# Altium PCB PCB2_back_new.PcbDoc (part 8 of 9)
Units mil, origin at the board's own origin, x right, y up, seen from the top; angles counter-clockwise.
Board outline 6299 x 3937 mil, 4 copper layers (TopLayer, GROUND, VCC, BottomLayer); 253 components, 421 nets, 2085 pads, 712 vias.
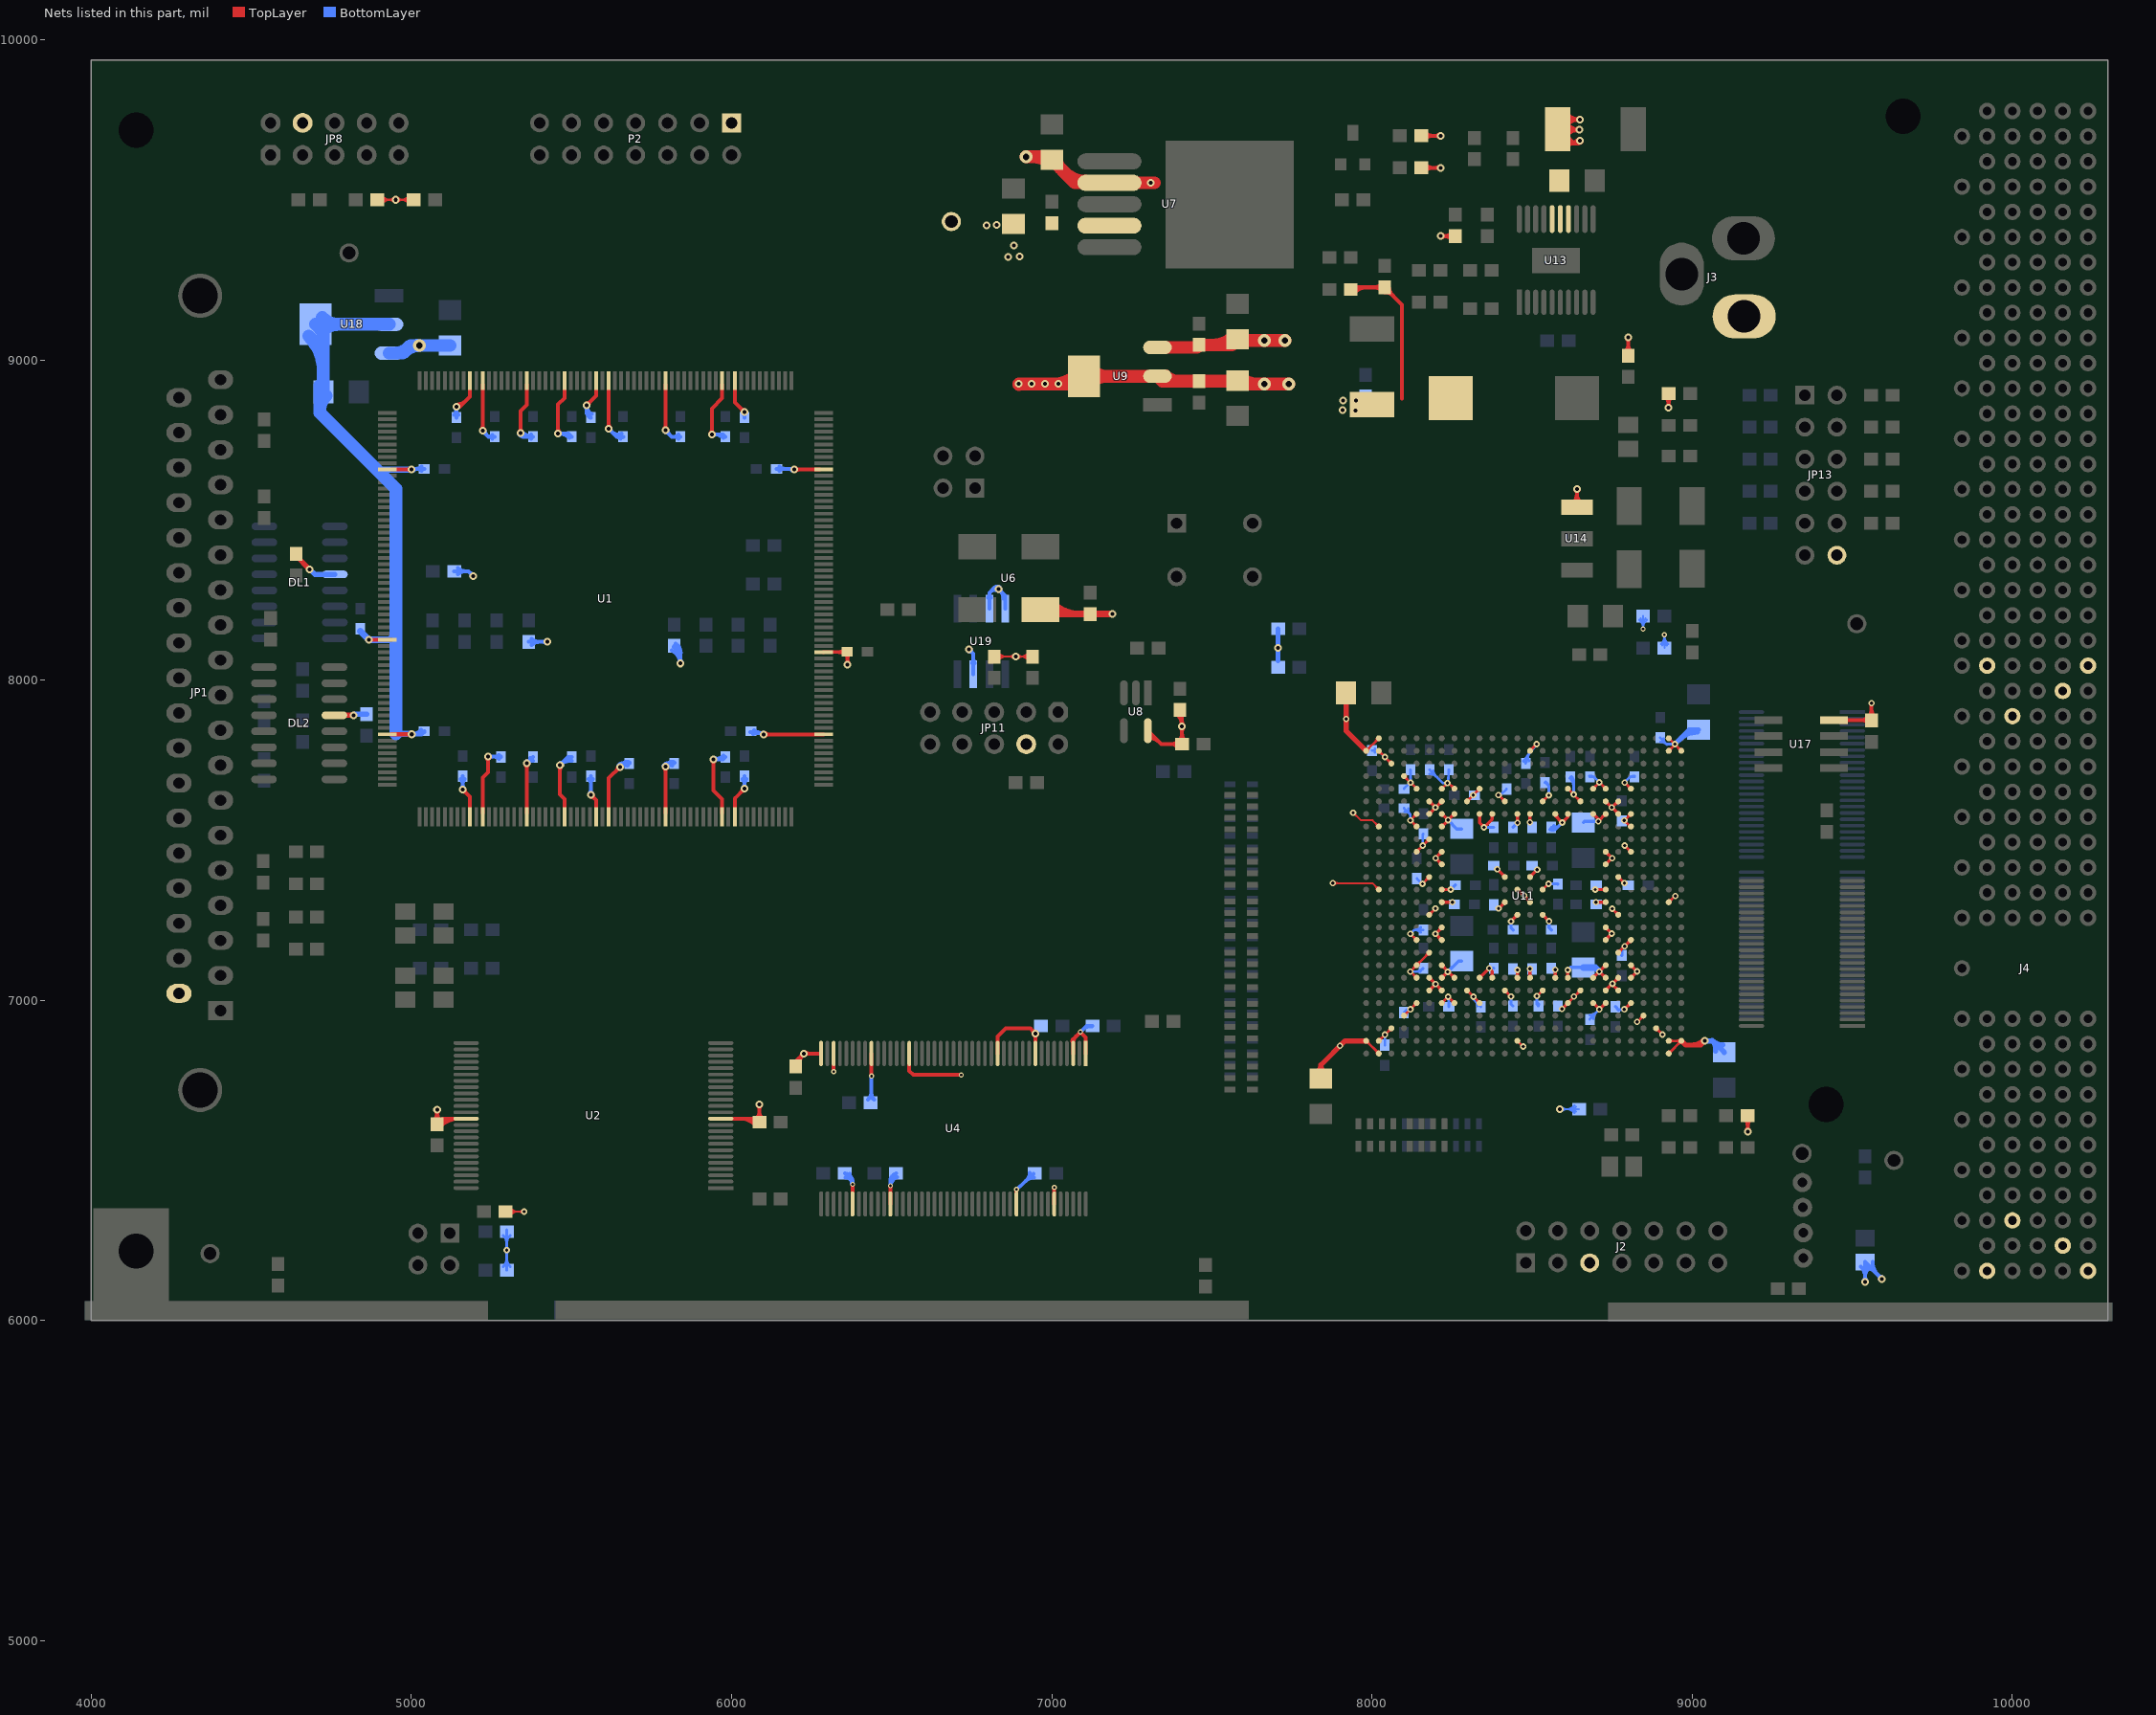
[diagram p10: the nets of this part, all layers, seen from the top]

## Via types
v1: diameter 16, hole 8, TopLayer to BottomLayer, 311 vias
v2: diameter 20, hole 10, TopLayer to BottomLayer, 202 vias
v3: diameter 24, hole 12, TopLayer to BottomLayer, 179 vias
v4: diameter 40, hole 20, TopLayer to BottomLayer, 12 vias
v5: diameter 30, hole 15, TopLayer to BottomLayer, 8 vias

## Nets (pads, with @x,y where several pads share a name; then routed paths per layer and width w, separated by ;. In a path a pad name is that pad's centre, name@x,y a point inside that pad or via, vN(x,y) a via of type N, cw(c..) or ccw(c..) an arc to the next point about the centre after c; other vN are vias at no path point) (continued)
V1.4: C23.1 C92.2 C104.1 C105.2 C106.1 C107.1 C111.1 C112.2 C113.1 C114.1 C115.1 C121.1 C122.1 C123.1 C124.1 C125.1 C126.1 C129.1 C130.2 C131.1 C135.1 C136.1 C137.1 C138.1 L1.2 R38.2 R41.2 U11.AA6 U11.AA7 U11.AA20 U11.AA21 U11.F6 U11.F7 U11.F20 U11.F21 U11.G6 U11.G7 U11.G8 U11.G10 U11.G11 U11.G13 U11.G14 U11.G16 U11.G17 U11.G19 U11.G20 U11.G21 U11.H7 U11.H20 U11.K7 U11.K20 U11.L7 U11.L20 U11.M12 U11.M14 U11.N7 U11.N13 U11.N15 U11.N20 U11.P7 U11.P12 U11.P14 U11.P20 U11.R13 U11.R15 U11.T7 U11.T20 U11.U7 U11.U20 U11.W20 U11.Y6 U11.Y7 U11.Y8 U11.Y10 U11.Y11 U11.Y13 U11.Y14 U11.Y16 U11.Y17 U11.Y19 U11.Y20 U11.Y21 | length 3757.4
  TopLayer w8: v2@8473,7327 v2@8474,7326 ; U11.P12@8532.93,7345.81 v2(8551.12,7364)
  TopLayer w10: U11.F21@8178.6,7030.85 v2(8198.23,7050.48) ; U11.F21@8178.6,7035.1 ccw(c8178.6,7045.37) 8185.86,7038.11 ccw(c8193.11,7030.85) U11.F21@8182.85,7030.85 ; U11.G21@8178.6,7065.97 cw(c8178.6,7055.7) 8185.86,7062.96 cw(c8193.11,7070.22) U11.G21@8182.85,7070.22 ; U11.G21@8178.6,7070.22 U11.F20@8217.97,7030.85 ; U11.Y21@8178.6,7582.03 v2@8198.39,7601.83 ; U11.Y21@8178.6,7586.28 ccw(c8178.6,7596.55) 8185.86,7589.29 ccw(c8193.11,7582.03) U11.Y21@8182.85,7582.03 ; U11.AA21@8178.6,7617.15 cw(c8178.6,7606.89) 8185.86,7614.14 cw(c8193.11,7621.4) U11.AA21@8182.85,7621.4 ; U11.AA21@8178.6,7621.4 v2(8198.17,7601.83) v2@8198.39,7601.83 ; 8209.74,7195.99 ccw(c8217.97,7204.21) U11.K20@8217.97,7192.58 ; 8211.11,7194.62 cw(c8204.82,7188.33) U11.K20@8213.72,7188.33 ; U11.F20@8213.72,7030.85 ccw(c8203.45,7030.85) 8210.71,7038.11 ccw(c8217.97,7045.37) U11.F20@8217.97,7035.1 ; U11.L20@8213.72,7227.7 cw(c8203.45,7227.7) 8210.71,7220.44 cw(c8217.97,7213.18) U11.L20@8217.97,7223.45 ; U11.T20@8213.72,7424.55 ccw(c8203.45,7424.55) 8210.71,7431.81 ccw(c8217.97,7439.07) U11.T20@8217.97,7428.8 ; U11.U20@8213.72,7463.92 cw(c8203.45,7463.92) 8210.71,7456.66 cw(c8217.97,7449.4) U11.U20@8217.97,7459.67 ; U11.AA20@8213.72,7621.4 cw(c8203.45,7621.4) 8210.71,7614.14 cw(c8217.97,7606.89) U11.AA20@8217.97,7617.15 ; U11.G20@8217.97,7070.22 v2(8236.57,7088.82) ; U11.G20@8217.97,7074.47 ccw(c8217.97,7084.74) 8225.23,7077.48 ccw(c8232.49,7070.22) U11.G20@8222.22,7070.22 ; U11.H20@8217.97,7105.34 cw(c8217.97,7095.07) 8225.23,7102.33 cw(c8232.49,7109.59) U11.H20@8222.22,7109.59 ; U11.H20@8217.97,7109.59 U11.G19@8257.34,7070.22 ; U11.K20@8217.97,7188.33 8217.4,7188.33 v2(8198,7207.73) U11.L20@8217.97,7227.7 ; U11.N20@8217.97,7306.44 v2(8250.57,7306.44) ; U11.P20@8217.97,7345.81 v2(8245.81,7345.81) ; U11.T20@8217.97,7424.55 v2(8199,7443.52) 8199,7444.95 U11.U20@8217.97,7463.92 ; U11.W20@8217.97,7542.66 8237.65,7562.35 v2@8238.12,7562.81 ; U11.W20@8217.97,7546.91 ccw(c8217.97,7557.18) 8225.23,7549.92 ccw(c8232.49,7542.66) U11.W20@8222.22,7542.66 ; U11.Y20@8217.97,7577.78 cw(c8217.97,7567.52) 8225.23,7574.77 cw(c8232.49,7582.03) U11.Y20@8222.22,7582.03 ; U11.Y20@8217.97,7582.03 v2(8237.19,7562.81) v2@8238.12,7562.81 ; U11.AA20@8217.97,7621.4 v2@8198.39,7601.83 ; U11.N20@8220.97,7303.43 cw(c8228.23,7296.18) 8228.23,7306.44 cw(c8228.23,7316.71) U11.N20@8220.97,7309.45 ; U11.P20@8220.97,7342.8 cw(c8228.23,7335.55) 8228.23,7345.81 cw(c8228.23,7356.08) U11.P20@8220.97,7348.82 ; U11.G19@8253.09,7070.22 ccw(c8242.82,7070.22) 8250.08,7077.48 ccw(c8257.34,7084.74) U11.G19@8257.34,7074.47 ; U11.Y19@8253.09,7582.03 cw(c8242.82,7582.03) 8250.08,7574.77 cw(c8257.34,7567.52) U11.Y19@8257.34,7577.78 ; U11.Y19@8257.34,7582.03 v2@8238.12,7562.81 ; U11.Y17@8333.07,7579.03 cw(c8325.81,7571.77) 8336.08,7571.77 cw(c8346.34,7571.77) U11.Y17@8339.08,7579.03 ; U11.G17@8336.08,7070.22 v2(8365.86,7100) 8375.45,7090.41 U11.G16@8375.45,7070.22 ; U11.G17@8336.08,7074.47 ccw(c8336.08,7084.74) 8343.34,7077.48 ccw(c8350.6,7070.22) U11.G17@8340.33,7070.22 ; U11.Y17@8336.08,7582.03 8336.08,7553.92 v2(8350,7540) 8375.45,7565.45 U11.Y16@8375.45,7582.03 ; U11.G16@8372.44,7073.23 ccw(c8365.18,7080.49) 8375.45,7080.49 ccw(c8385.71,7080.49) U11.G16@8378.46,7073.23 ; U11.Y16@8372.44,7579.03 cw(c8365.18,7571.77) 8375.45,7571.77 cw(c8385.71,7571.77) U11.Y16@8378.46,7579.03 ; v2(8391,7409) U11.R15@8414.82,7385.18 ; v2(8395.38,7287) U11.N15@8414.82,7306.44 ; U11.N15@8410.57,7306.44 cw(c8400.3,7306.44) 8407.56,7299.18 cw(c8414.82,7291.92) U11.N15@8414.82,7302.19 ; U11.R15@8410.57,7385.18 ccw(c8400.3,7385.18) 8407.56,7392.44 ccw(c8414.82,7399.7) U11.R15@8414.82,7389.43 ; v2(8434,7246.88) U11.M14@8454.19,7267.07 ; U11.M14@8449.94,7267.07 cw(c8439.67,7267.07) 8446.93,7259.81 cw(c8454.19,7252.55) U11.M14@8454.19,7262.82 ; U11.Y14@8451.18,7579.03 cw(c8443.92,7571.77) 8454.19,7571.77 cw(c8464.45,7571.77) U11.Y14@8457.2,7579.03 ; v2(8454,7095) 8454.19,7094.81 U11.G14@8454.19,7070.22 ; U11.P14@8454.19,7341.56 cw(c8454.19,7331.29) 8461.45,7338.55 cw(c8468.71,7345.81) U11.P14@8458.44,7345.81 ; U11.P14@8454.19,7345.81 8473,7327 v2(8475,7327) 8493.56,7308.44 U11.N13@8493.56,7306.44 ; v2(8454.19,7554.19) U11.Y14@8454.19,7582.03 ; U11.G13@8490.55,7073.23 ccw(c8483.29,7080.49) 8493.56,7080.49 ccw(c8503.82,7080.49) U11.G13@8496.57,7073.23 ; U11.Y13@8490.55,7579.03 cw(c8483.29,7571.77) 8493.56,7571.77 cw(c8503.82,7571.77) U11.Y13@8496.57,7579.03 ; U11.G13@8493.56,7070.22 v2(8493.56,7098.56) ; U11.R13@8493.56,7385.18 v2(8516,7407.62) ; U11.R13@8493.56,7389.43 ccw(c8493.56,7399.7) 8500.82,7392.44 ccw(c8508.08,7385.18) U11.R13@8497.81,7385.18 ; v2(8493.56,7555.56) U11.Y13@8493.56,7582.03 ; U11.M12@8532.93,7262.82 cw(c8532.93,7252.55) 8540.19,7259.81 cw(c8547.45,7267.07) U11.M12@8537.18,7267.07 ; U11.M12@8532.93,7267.07 v2(8553,7247) ; U11.G11@8569.29,7073.23 ccw(c8562.03,7080.49) 8572.3,7080.49 ccw(c8582.56,7080.49) U11.G11@8575.31,7073.23 ; U11.G11@8572.3,7070.22 v2(8572.3,7095.7) ; U11.Y11@8572.3,7582.03 8572.3,7576.7 v2(8594,7555) 8611.67,7572.67 ; U11.Y11@8576.55,7582.03 ccw(c8599.69,7582.03) 8583.33,7565.67 ; U11.Y10@8608.87,7578.83 cw(c8603.49,7572.67) 8611.67,7572.67 ; U11.G10@8611.67,7070.22 v2(8611.67,7094.67) ; U11.Y10@8611.67,7582.03 8611.67,7572.67 ; U11.Y10@8614.47,7578.83 ccw(c8619.85,7572.67) 8611.67,7572.67 ; U11.G8@8690.41,7070.22 8690.41,7070.41 8729.59,7109.59 U11.H7@8729.78,7109.59 ; U11.G8@8690.41,7074.47 ccw(c8690.41,7084.28) 8697.35,7077.35 ; U11.Y8@8690.41,7577.78 cw(c8690.41,7567.52) 8697.67,7574.77 cw(c8704.93,7582.03) U11.Y8@8694.66,7582.03 ; U11.Y8@8690.41,7582.03 8706.75,7565.69 v2(8706.75,7559) U11.Y7@8729.78,7582.03 ; U11.G8@8694.66,7070.22 cw(c8705.38,7070.22) 8697.8,7077.8 ; v2(8697.19,7345.81) U11.P7@8729.78,7345.81 ; v2(8699.56,7306.44) U11.N7@8729.78,7306.44 ; v2(8710,7090) U11.G7@8729.78,7070.22 ; 8722.2,7102.2 cw(c8729.78,7094.62) U11.H7@8729.78,7105.34 ; 8722.65,7102.65 ccw(c8715.72,7109.59) U11.H7@8725.53,7109.59 ; U11.G7@8725.53,7070.22 ccw(c8715.26,7070.22) 8722.52,7077.48 ccw(c8729.78,7084.74) U11.G7@8729.78,7074.47 ; U11.Y7@8725.53,7582.03 cw(c8715.26,7582.03) 8722.52,7574.77 cw(c8729.78,7567.52) U11.Y7@8729.78,7577.78 ; U11.N7@8726.77,7303.43 ccw(c8719.51,7296.18) 8719.51,7306.44 ccw(c8719.51,7316.71) U11.N7@8726.77,7309.45 ; U11.P7@8726.77,7342.8 ccw(c8719.51,7335.55) 8719.51,7345.81 ccw(c8719.51,7356.08) U11.P7@8726.77,7348.82 ; U11.F7@8729.78,7030.85 U11.G6@8769.15,7070.22 ; U11.F7@8729.78,7035.1 ccw(c8729.78,7045.37) 8737.04,7038.11 ccw(c8744.3,7030.85) U11.F7@8734.03,7030.85 ; U11.K7@8729.78,7188.33 8729.78,7189.26 v2(8749,7208.48) U11.L7@8729.78,7227.7 ; U11.L7@8729.78,7223.45 cw(c8729.78,7213.18) 8737.04,7220.44 cw(c8744.3,7227.7) U11.L7@8734.03,7227.7 ; U11.T7@8729.78,7424.55 8748.93,7443.7 v2(8750,7443.7) U11.U7@8729.78,7463.92 ; U11.T7@8729.78,7428.8 ccw(c8729.78,7439.07) 8737.04,7431.81 ccw(c8744.3,7424.55) U11.T7@8734.03,7424.55 ; U11.U7@8729.78,7459.67 cw(c8729.78,7449.4) 8737.04,7456.66 cw(c8744.3,7463.92) U11.U7@8734.03,7463.92 ; U11.AA7@8729.78,7617.15 cw(c8729.78,7606.89) 8737.04,7614.14 cw(c8744.3,7621.4) U11.AA7@8734.03,7621.4 ; U11.AA7@8729.78,7621.4 U11.Y6@8769.15,7582.03 ; U11.K7@8734.03,7188.33 cw(c8746.54,7188.33) 8737.69,7197.18 ; v2(8748.94,7602.24) 8768.09,7621.4 U11.AA6@8769.15,7621.4 ; v2(8750.67,7051.74) 8750.67,7049.33 U11.F6@8769.15,7030.85 U11.F6@8769.15,7032.32 ; 8760.09,7613.4 cw(c8769.15,7604.34) U11.AA6@8769.15,7617.15 ; U11.F6@8764.9,7030.85 ccw(c8754.63,7030.85) 8761.89,7038.11 ccw(c8769.15,7045.37) U11.F6@8769.15,7035.1 ; U11.G6@8764.9,7070.22 cw(c8754.63,7070.22) 8761.89,7062.96 cw(c8769.15,7055.7) U11.G6@8769.15,7065.97 ; U11.Y6@8764.9,7582.03 ccw(c8754.63,7582.03) 8761.89,7589.29 ccw(c8769.15,7596.55) U11.Y6@8769.15,7586.28
  TopLayer w12: R38.2@7933.46,9220 7940,9226.54 R41.2@8040,9226.54 8094,9172.54 8094,8879 ; R38.2@7936.62,9218.81 cw(c7955.28,9200.15) 7955.28,9226.54 ; R38.2@7945.11,9210.32 cw(c7984.25,9171.18) 7984.25,9226.54 ; R41.2@8030.32,9216.86 ccw(c8006.96,9193.5) 8006.96,9226.54 ccw(c8006.96,9259.57) R41.2@8030.32,9236.21 ; R41.2@8040,9210.88 cw(c8040,9173.09) 8066.72,9199.81 ; R41.2@8053.68,9224.57 ccw(c8081.97,9224.57) 8061.97,9204.57
  BottomLayer w10: v2(8236.57,7088.82) 8270.31,7122.57 C104.1@8280,7122.57 ; v2(8237.19,7562.81) 8264.88,7535.12 C106.1@8280,7535.12 ; v2(8245.81,7345.81) C107.1@8260,7360 ; v2(8350,7540) C115.1@8380,7540 ; v2(8365.86,7100) C111.1@8380,7100 ; v2(8434,7246.88) 8434,7226.99 C112.2@8440.99,7220 ; C126.1@8440,7540 v2(8454.19,7554.19) ; v2(8551.12,7364) 8578.99,7364 C130.2@8580,7362.99 ; v2(8553,7247) 8553,7227 C123.1@8560,7220 ; C131.1@8555.01,7533.83 ccw(c8563.51,7548.59) 8575.55,7536.55 ; C131.1@8560,7540 8579,7540 ; C131.1@8568.24,7534.34 cw(c8579,7526.95) 8579,7540 ; C131.1@8568.24,7545.66 ccw(c8579,7553.05) 8579,7540 ; v2(8594,7555) 8579,7540 ; v2(8611.67,7094.67) 8619.57,7102.57 C135.1@8660,7102.57 ; C138.1@8660,7555.12 8663.88,7559 v2(8706.75,7559)
  BottomLayer w12: v3(7949,8842) 7980,8873 C92.2@7980,8886.54 ; v3@7949,8848 ccw(c7949,8862.49) 7959.24,8852.24 ccw(c7969.49,8842) v3@7955,8842 ; v3@7954.78,8847.78 ccw(c7925.65,8876.92) C92.2@7966.45,8882.66 ; 7971.8,8864.8 ccw(c7955.48,8881.11) C92.2@7978.33,8884.33
  BottomLayer w20: C135.1@8660,7102.57 8697.43,7102.57 v2(8710,7090)
  other v3: 7908,8843 7909,8873 7950,8873
V1.5: C13.1 C17.2 C49.1 C51.1 C52.1 C53.1 C54.1 C58.1 C60.1 C61.1 C63.1 C64.1 C67.1 C69.1 FB6.1 FB7.1 U1.72 U1.81 U1.90 U1.97 U1.103 U1.110 U1.191 U1.198 U1.204 U1.211 U1.220 U1.229 U9.2 | length 5264.2
  TopLayer w8: 5220,8857 5222.14,8859.14 ; U1.97@5478.05,8922.31 U1.97@5480,8920.35
  TopLayer w12: v3@5217.9,8783.1 ccw(c5207.66,8793.34) 5222.14,8793.34 ccw(c5236.63,8793.34) v3@5226.38,8783.1 ; U1.191@5222.14,7585.69 5222.14,7695.14 5239,7712 v3(5239,7761) ; v3(5222.14,8778.86) U1.110@5222.14,8922.31 ; v3@5234.76,7756.76 cw(c5224.51,7746.51) 5239,7746.51 cw(c5253.49,7746.51) v3@5243.24,7756.76 ; v3@5336.76,8775.24 ccw(c5326.51,8785.49) 5341,8785.49 ccw(c5355.49,8785.49) v3@5345.24,8775.24 ; v3(5341,8771) 5341,8840.13 5359.94,8859.06 U1.103@5359.94,8922.31 ; v3@5355.69,7735.69 cw(c5345.45,7725.45) 5359.94,7725.45 cw(c5374.42,7725.45) v3@5364.18,7735.69 ; U1.198@5359.94,7585.69 v3(5359.94,7739.94) ; v3@5453.76,8774.24 ccw(c5443.51,8784.49) 5458,8784.49 ccw(c5472.49,8784.49) v3@5462.24,8774.24 ; v3(5458,8770) 5458,8861 5478.05,8881.05 U1.97@5478.05,8922.31 ; v3@5459.76,7730.76 cw(c5449.51,7720.51) 5464,7720.51 cw(c5478.49,7720.51) v3@5468.24,7730.76 ; v3(5464,7735) 5464,7643 5478.05,7628.95 U1.204@5478.05,7585.69 ; v3@5611.6,8789.4 ccw(c5601.36,8799.64) 5615.84,8799.64 ccw(c5630.33,8799.64) v3@5620.09,8789.4 ; U1.211@5615.84,7585.69 5615.84,7693.84 v3(5651,7729) ; v3(5615.84,8785.16) U1.90@5615.84,8922.31 ; v3@5645,7729 cw(c5630.51,7729) 5640.76,7718.76 cw(c5651,7708.51) v3@5651,7723 ; v3@5788.77,7725.77 cw(c5778.52,7715.52) 5793.01,7715.52 cw(c5807.49,7715.52) v3@5797.25,7725.77 ; v3@5788.77,8784.23 ccw(c5778.52,8794.48) 5793.01,8794.48 ccw(c5807.49,8794.48) v3@5797.25,8784.23 ; U1.220@5793.01,7585.69 v3(5793.01,7730.01) ; v3(5793.01,8779.99) U1.81@5793.01,8922.31 ; v3@5933.76,8771.24 ccw(c5923.51,8781.49) 5938,8781.49 ccw(c5952.49,8781.49) v3@5942.24,8771.24 ; v3(5938,8767) 5938,8848 5970.17,8880.17 U1.72@5970.17,8922.31 ; v3@5938.76,7748.76 cw(c5928.51,7738.51) 5943,7738.51 cw(c5957.49,7738.51) v3@5947.24,7748.76 ; v3(5943,7753) 5943,7655 5970.17,7627.83 U1.229@5970.17,7585.69
  TopLayer w40: v3@6897,8923 v3(6897,8925) U9.2@7095,8925 ; 7005.85,8925 ccw(c7005.85,9028.15) U9.2@7078.79,8955.21 ; 7049.3,8925 cw(c7049.3,8883.3) U9.2@7078.79,8912.79 ; U9.2@7100,8949 U9.2@7330,8949 7345.54,8933.46 7578.35,8933.46 7586.81,8925 v4(7740,8925) ; U9.2@7121.21,8927.79 cw(c7172.43,8876.57) 7172.43,8949 cw(c7172.43,9021.43) U9.2@7121.21,8970.21 ; U9.2@7354.71,8949.71 ccw(c7393.92,8988.92) 7393.92,8933.46 ; 7544.32,8933.46 ccw(c7544.32,8966.86) C13.1@7567.93,8943.25 ; C13.1@7592.07,8943.25 ccw(c7636.12,8987.3) 7636.12,8925
  BottomLayer w12: v3@5222.14,8772.86 cw(c5222.14,8758.37) 5232.38,8768.62 cw(c5242.63,8778.86) v3@5228.14,8778.86 ; v3(5222.14,8778.86) 5241,8760 ; v3(5239,7761) 5279,7761 C49.1@5280,7760 ; v3@5243.24,7756.76 cw(c5253.49,7746.51) 5253.49,7761 cw(c5253.49,7775.49) v3@5243.24,7765.24 ; C51.1@5253.04,8754.3 ccw(c5241,8744.45) 5241,8760 ; C51.1@5253.04,8765.7 cw(c5241,8775.55) 5241,8760 ; 5255.86,7761 cw(c5255.86,7735.86) C49.1@5273.64,7753.64 ; C51.1@5260,8760 5241,8760 ; 5260.69,7761 ccw(c5260.69,7779.31) C49.1@5273.64,7766.36 ; v3@5336.6,8766.92 ccw(c5352.47,8781.66) 5352.47,8760 ; v3@5341,8765 cw(c5341,8750.51) 5351.24,8760.76 cw(c5361.49,8771) v3@5347,8771 ; v3(5341,8771) 5352,8760 C53.1@5380,8760 cw(c5380,8807.23) v3@5345.4,8775.08 ; v3(5359.94,7739.94) C52.1@5380,7760 ; v3@5359.94,7745.94 ccw(c5359.94,7760.42) 5370.18,7750.18 ccw(c5380.42,7739.94) v3@5365.94,7739.94 ; v3@5360.37,7740.37 cw(c5380,7720.74) C52.1@5380,7748.5 ; FB6.1@5366,8119.54 v3(5424.54,8119.54) ; C52.1@5366.4,7746.4 ccw(c5355.31,7757.5) C52.1@5371,7757.5 ; C53.1@5373.64,8753.64 ccw(c5358.27,8738.27) 5358.27,8760 ccw(c5358.27,8781.73) C53.1@5373.64,8766.36 ; FB6.1@5375.68,8109.86 cw(c5399.04,8086.5) 5399.04,8119.54 cw(c5399.04,8152.57) FB6.1@5375.68,8129.21 ; v3@5420.29,8115.29 ccw(c5410.05,8105.05) 5410.05,8119.54 ccw(c5410.05,8134.02) v3@5420.29,8123.78 ; v3(5458,8770) 5490,8770 C58.1@5500,8760 ; v3@5460.17,8770 cw(c5460.17,8722.67) C58.1@5493.64,8756.14 ; v3@5461.59,7732.59 cw(c5500,7694.18) C54.1@5500,7748.5 ; v3@5462.24,8765.76 cw(c5472.49,8755.51) 5472.49,8770 cw(c5472.49,8784.49) v3@5462.24,8774.24 ; v3(5464,7735) 5489,7760 C54.1@5500,7760 ; v3@5464,7741 ccw(c5464,7755.49) 5474.24,7745.24 ccw(c5484.49,7735) v3@5470,7735 ; 5482.08,7753.08 cw(c5500,7735.15) C54.1@5500,7760.5 ; v3@5615.84,8779.16 cw(c5615.84,8764.67) 5626.09,8774.91 cw(c5636.33,8785.16) v3@5621.84,8785.16 ; v3(5615.84,8785.16) 5641,8760 ; 5626.59,8774.41 ccw(c5643.78,8791.6) C61.1@5655.62,8770.36 ; 5637.83,8763.17 ccw(c5651.82,8777.17) C61.1@5661.46,8759.88 ; v3@5645.76,7731.93 cw(c5659.53,7724.23) 5659.53,7740 ; v3(5651,7729) 5662,7740 ; v3@5651,7735 ccw(c5651,7749.49) 5661.24,7739.24 ccw(c5671.49,7729) v3@5657,7729 ; v3@5653,7731 cw(c5664.86,7719.14) C60.1@5674.71,7732.72 ; C61.1@5653.04,8754.3 ccw(c5641,8744.45) 5641,8760 ; C61.1@5653.04,8765.7 cw(c5641,8775.55) 5641,8760 ; v3@5655.56,7733.56 cw(c5674.13,7714.99) C60.1@5680.76,7740.4 ; v3@5656.24,7726.07 cw(c5680,7712.77) C60.1@5680,7740 5662,7740 ; C61.1@5660,8760 5641,8760 ; 5662.94,7740.94 cw(c5673.22,7730.66) C60.1@5681.76,7742.43 ; C60.1@5672.8,7734.6 ccw(c5662,7726.5) 5662,7740 ; C60.1@5672.8,7745.4 cw(c5662,7753.5) 5662,7740 ; v3@5787.75,7732.89 cw(c5799.75,7726.32) 5799.75,7740 ; v3(5793.01,7730.01) 5803,7740 ; v3@5793.01,8773.99 cw(c5793.01,8759.51) 5803.25,8769.75 cw(c5813.49,8779.99) v3@5799.01,8779.99 ; v3(5793.01,8779.99) 5813,8760 C64.1@5840,8760 ; v3@5793.11,7736.01 ccw(c5793.36,7749.64) 5803,7740 ; v3@5794.5,7731.5 cw(c5805.29,7720.71) C63.1@5814.54,7732.84 ; v3@5797.47,7734.47 cw(c5814.11,7717.83) C63.1@5820.86,7740.37 ; v3@5798.27,7727.13 cw(c5820,7715.23) C63.1@5820,7740 5803,7740 ; v3@5799.01,7730.11 cw(c5812.64,7730.36) 5803,7740 ; 5804.2,7741.2 cw(c5813.69,7731.72) C63.1@5821.82,7742.39 ; C63.1@5812.56,7734.94 ccw(c5803,7728.45) 5803,7740 ; C63.1@5812.56,7745.06 cw(c5803,7751.55) 5803,7740 ; FB7.1@5813.54,8092.5 cw(c5789.89,8048.33) v3@5840,8048.33 ; FB7.1@5819.2,8103.08 cw(c5800.62,8068.36) 5840,8068.36 ; FB7.1@5820,8106.54 5840,8086.54 v3(5840,8052) ; FB7.1@5822.64,8091.14 cw(c5826.57,8071.14) 5840.98,8085.55 cw(c5858.66,8103.23) FB7.1@5833.68,8104.09 ; FB7.1@5824.87,8113.66 cw(c5811.34,8088.4) 5840,8088.4 ; C64.1@5833.64,8753.64 ccw(c5818.27,8738.27) 5818.27,8760 ccw(c5818.27,8781.73) C64.1@5833.64,8766.36 ; v3@5835.76,8056.24 ccw(c5825.51,8066.49) 5840,8066.49 ccw(c5854.49,8066.49) v3@5844.24,8056.24 ; v3(5938,8767) 5973,8767 C69.1@5980,8760 ; v3@5942.24,8762.76 cw(c5952.49,8752.51) 5952.49,8767 cw(c5952.49,8781.49) v3@5942.24,8771.24 ; v3(5943,7753) 5973,7753 C67.1@5980,7760 ; v3@5947.24,7748.76 cw(c5957.49,7738.51) 5957.49,7753 cw(c5957.49,7767.49) v3@5947.24,7757.24 ; v3@5947.41,7753 ccw(c5947.41,7790.09) C67.1@5973.64,7763.86 ; v3@5947.41,8767 cw(c5947.41,8729.91) C69.1@5973.64,8756.14
  other v3: 6937,8925 6978,8925 7020,8925
  other v4: 7664,8925
V2.5: C38.1 C40.1 C45.1 C47.1 U1.130 U1.157 U1.172 U18.2 | length 2667
  TopLayer w12: v3(4866.95,8126.05) U1.157@4937.69,8126.05 ; U1.172@4937.69,7830.77 v3(5000.77,7830.77) ; U1.130@4937.69,8657.54 v3(5000.54,8657.54) ; v3@4996.3,8653.3 ccw(c4986.06,8643.06) 4986.06,8657.54 ccw(c4986.06,8672.03) v3@4996.3,8661.79 ; v3@4996.53,7826.53 ccw(c4986.29,7816.29) 4986.29,7830.77 ccw(c4986.29,7845.26) v3@4996.53,7835.01
  BottomLayer w8: C40.1@4840,8153 C40.1@4840,8160 ; v3(5000.54,8657.54) v3@5003,8660
  BottomLayer w12: v3@5003,8660 C47.1@5040,8660 ; v3@5004.79,8653.3 cw(c5020.96,8637.13) 5020.96,8660 ; v3@5005.01,7826.53 cw(c5015.26,7816.29) 5015.26,7830.77 cw(c5015.26,7845.26) v3@5005.01,7835.01 ; C45.1@5024.95,7830.77 ccw(c5024.95,7849.53) C45.1@5039.89,7838.19 ; C45.1@5030.33,7845.44 cw(c5000.77,7867.88) v3(5000.77,7830.77) 5030.77,7830.77 C45.1@5040,7840 ; C47.1@5031.14,8653.64 ccw(c5015.77,8638.27) 5015.77,8660 ccw(c5015.77,8681.73) C47.1@5031.14,8666.36
  BottomLayer w20: C40.1@4840,8153 v3(4866.95,8126.05) 4931.05,8126.05 4952,8147 ; 4901.54,8657.54 v3(5000.54,8657.54) ; 4952,7832 4999.54,7832 v3(5000.77,7830.77)
  BottomLayer w40: U18.2@4678.79,9074.79 cw(c4567.5,8963.5) 4724.88,8963.5 ; 4713.46,8840.75 cw(c4780.2,8840.75) C38.1@4733.01,8887.93 ; C38.1@4713.46,8920 4713.46,8835.54 4952,8597 4952,7832 ; U18.2@4721.21,9089.79 cw(c4772.43,9038.57) 4772.43,9111 cw(c4772.43,9183.43) U18.2@4721.21,9132.21 ; C38.1@4724.88,8900 4724.88,9086.12 U18.2@4700,9111 U18.2@4930,9111
V3.3: C1.1 C2.1 C5.2 C7.1 C8.2 C10.1 C12.1 C15.2 C16.2 C19.2 C20.1 C21.1 C37.2 C44.1 C48.1 C56.1 C57.1 C71.1 C73.1 C75.1 C77.1 C79.2 C80.2 C81.2 C82.2 C83.2 C84.2 C91.1 C93.1 C94.1 C95.1 C96.1 C97.1 C98.1 C99.1 C100.1 C101.1 C102.1 C103.1 C108.1 C109.1 C110.1 C116.1 C119.1 C120.1 C127.1 C128.1 C132.1 C133.1 C134.1 C139.1 C140.1 C141.1 C142.1 C143.1 C144.1 C145.1 C146.1 C147.1 DL1.4 DL2.13 FB4.1 J2.5 JP1.20 JP8.4 JP11.4 P2.1 pad.9 R15.2 R18.2 R19.2 R24.2 R26.2 R30.2 R56.2 R63.1 R64.1 R65.2 R76.1 R77.1 R80.2 R81.2 R82.2 U1.9 U1.22 U1.51 U1.70 U1.92 U1.112 U1.189 U1.209 U1.231 U2.12 U2.37 U4.1 U4.3 U4.9 U4.15 U4.29 U4.35 U4.41 U4.43 U4.49 U4.55 U4.75 U4.81 U6.4 U7.4 U8.5 U11.A2 U11.A25 U11.AA9 U11.AA12 U11.AA15 U11.AA18 U11.AB5 U11.AB7 U11.AB8 U11.AB10 U11.AB17 U11.AB19 U11.AB20 U11.AB22 U11.AC23 U11.AD24 U11.AE1 U11.AE2 U11.AE13 U11.AE25 U11.AE26 U11.AF2 U11.AF25 U11.B1 U11.B2 U11.B14 U11.B25 U11.B26 U11.C3 U11.C24 U11.D4 U11.D23 U11.E5 U11.E7 U11.E8 U11.E10 U11.E17 U11.E19 U11.E20 U11.E22 U11.F9 U11.F12 U11.F15 U11.F18 U11.G5 U11.G22 U11.H5 U11.H22 U11.J6 U11.J21 U11.K5 U11.K22 U11.M6 U11.M21 U11.N2 U11.P25 U11.R6 U11.R21 U11.U5 U11.U22 U11.V21 U11.W5 U11.W22 U11.W25 U11.Y5 U11.Y22 U14.1 U17.8 U19.3 U19.7 U19.8 | length 14541.5
  TopLayer w6: R19.2@5293.46,6340 v2(5352,6340) ; R19.2@5302.99,6332.44 cw(c5321.23,6314.2) 5321.23,6340 cw(c5321.23,6365.8) R19.2@5302.99,6347.56 ; R19.2@5307.23,6328.2 cw(c5335.71,6299.72) 5335.71,6340 cw(c5335.71,6380.28) R19.2@5307.23,6351.8 ; v2@5347.05,6335.05 ccw(c5335.1,6323.1) 5335.1,6340 ccw(c5335.1,6356.9) v2@5347.05,6344.95 ; R24.2@6820,8073.46 R26.2@6940,8073.46 ; R24.2@6827.56,8065.91 cw(c6845.8,8047.67) 6845.8,8073.46 cw(c6845.8,8099.26) R24.2@6827.56,8081.02 ; R24.2@6831.8,8061.67 cw(c6860.28,8033.18) 6860.28,8073.46 cw(c6860.28,8113.75) R24.2@6831.8,8085.26 ; v3@6881.64,8067.1 ccw(c6866.27,8051.74) 6866.27,8073.46 ccw(c6866.27,8095.19) v3@6881.64,8079.83 ; v3@6894.36,8067.1 cw(c6909.73,8051.74) 6909.73,8073.46 cw(c6909.73,8095.19) v3@6894.36,8079.83 ; R26.2@6928.2,8061.67 ccw(c6899.72,8033.18) 6899.72,8073.46 ccw(c6899.72,8113.75) R26.2@6928.2,8085.26 ; R26.2@6932.44,8065.91 ccw(c6914.2,8047.67) 6914.2,8073.46 ccw(c6914.2,8099.26) R26.2@6932.44,8081.02 ; v2(7877,7366) 8000.93,7366 U11.P25@8021.12,7345.81 ; v2@7881.95,7361.05 cw(c7893.9,7349.1) 7893.9,7366 cw(c7893.9,7382.9) v2@7881.95,7370.95 ; v2(7941,7586) 7965,7562 8001.78,7562 U11.W25@8021.12,7542.66 ; U11.P25@8014.87,7345.81 ccw(c7999.77,7345.81) 8010.44,7356.48 ccw(c8021.12,7367.16) U11.P25@8021.12,7352.06 ; U11.W25@8014.87,7542.66 ccw(c7999.77,7542.66) 8010.44,7553.33 ccw(c8021.12,7564.01) U11.W25@8021.12,7548.91
  TopLayer w8: R15.2@4893.46,9500 R18.2@5006.54,9500 ; R15.2@4906.52,9488.91 cw(c4933.3,9462.13) 4933.3,9500 cw(c4933.3,9537.87) R15.2@4906.52,9511.09 ; v3@4945.34,9494.34 ccw(c4931.69,9480.69) 4931.69,9500 ccw(c4931.69,9519.31) v3@4945.34,9505.66 ; v3@4956.66,9494.34 cw(c4970.31,9480.69) 4970.31,9500 cw(c4970.31,9519.31) v3@4956.66,9505.66 ; R18.2@4993.48,9488.91 ccw(c4966.7,9462.13) 4966.7,9500 ccw(c4966.7,9537.87) R18.2@4993.48,9511.09 ; U11.B26@7981.75,6868.12 cw(c7981.75,6855.44) 7990.71,6864.4 cw(c7999.68,6873.37) U11.B26@7987,6873.37 ; U11.B26@7981.75,6873.37 U11.A25@8021.12,6834 ; U11.AE26@7981.75,7778.88 U11.AF25@8021.12,7818.25 ; U11.AE26@7981.75,7784.13 ccw(c7981.75,7796.81) 7990.71,7787.85 ccw(c7999.68,7778.88) U11.AE26@7987,7778.88 ; U11.A25@8015.87,6834 ccw(c8003.19,6834) 8012.15,6842.97 ccw(c8021.12,6851.93) U11.A25@8021.12,6839.25 ; U11.AF25@8015.87,7818.25 cw(c8003.19,7818.25) 8012.15,7809.29 cw(c8021.12,7800.32) U11.AF25@8021.12,7813 ; U11.B25@8021.12,6873.37 U11.C24@8060.49,6912.74 ; U11.B25@8021.12,6878.62 ccw(c8021.12,6891.3) 8030.08,6882.34 ccw(c8039.05,6873.37) U11.B25@8026.37,6873.37 ; U11.AE25@8021.12,7773.63 cw(c8021.12,7760.95) 8030.08,7769.92 cw(c8039.05,7778.88) U11.AE25@8026.37,7778.88 ; U11.AE25@8021.12,7778.88 U11.AD24@8060.49,7739.51 ; U11.C24@8055.24,6912.74 cw(c8042.56,6912.74) 8051.52,6903.77 cw(c8060.49,6894.81) U11.C24@8060.49,6907.49 ; U11.AD24@8055.24,7739.51 ccw(c8042.56,7739.51) 8051.52,7748.48 ccw(c8060.49,7757.44) U11.AD24@8060.49,7744.76 ; U11.D23@8099.86,6952.11 8119.87,6972.13 U11.E22@8139.23,6991.48 ; U11.D23@8099.86,6957.36 ccw(c8099.86,6970.04) 8108.82,6961.08 ccw(c8117.79,6952.11) U11.D23@8105.11,6952.11 ; U11.AC23@8099.86,7694.89 cw(c8099.86,7682.21) 8108.82,7691.18 cw(c8117.79,7700.14) U11.AC23@8105.11,7700.14 ; U11.AC23@8099.86,7700.14 U11.AB22@8139.23,7660.77 ; v2(8120,7207.56) U11.K22@8139.23,7188.33 ; 8130.13,7079.51 cw(c8120.84,7070.22) U11.G22@8133.98,7070.22 ; 8130.58,7079.05 ccw(c8139.23,7087.7) U11.G22@8139.23,7075.47 ; U11.E22@8133.98,6991.48 cw(c8121.3,6991.48) 8130.26,6982.51 cw(c8139.23,6973.55) U11.E22@8139.23,6986.23 ; U11.H22@8133.98,7109.59 cw(c8121.3,7109.59) 8130.26,7100.63 cw(c8139.23,7091.66) U11.H22@8139.23,7104.34 ; U11.K22@8133.98,7188.33 ccw(c8121.3,7188.33) 8130.26,7197.3 ccw(c8139.23,7206.26) U11.K22@8139.23,7193.58 ; U11.W22@8133.98,7542.66 ccw(c8121.3,7542.66) 8130.26,7551.63 ccw(c8139.23,7560.59) U11.W22@8139.23,7547.91 ; U11.Y22@8133.98,7582.03 cw(c8121.3,7582.03) 8130.26,7573.07 cw(c8139.23,7564.1) U11.Y22@8139.23,7576.78 ; U11.G22@8139.23,7070.22 8139.23,7070.41 v2(8119.64,7090) U11.J21@8178.6,7148.96 ; U11.H22@8139.23,7114.84 ccw(c8139.23,7127.52) 8148.19,7118.56 ccw(c8157.16,7109.59) U11.H22@8144.48,7109.59 ; U11.U22@8139.23,7463.92 U11.V21@8178.6,7503.29 ; U11.U22@8139.23,7469.17 ccw(c8139.23,7481.85) 8148.19,7472.89 ccw(c8157.16,7463.92) U11.U22@8144.48,7463.92 ; U11.W22@8139.23,7542.66 v2(8120,7561.89) 8120,7562.8 U11.Y22@8139.23,7582.03 ; v2(8157.42,7364) U11.R21@8178.6,7385.18 ; U11.J21@8173.35,7148.96 cw(c8160.67,7148.96) 8169.63,7140 cw(c8178.6,7131.03) U11.J21@8178.6,7143.71 ; U11.R21@8173.35,7385.18 cw(c8160.67,7385.18) 8169.63,7376.22 cw(c8178.6,7367.25) U11.R21@8178.6,7379.93 ; U11.V21@8173.35,7503.29 cw(c8160.67,7503.29) 8169.63,7494.33 cw(c8178.6,7485.36) U11.V21@8178.6,7498.04 ; U11.M21@8178.6,7267.07 v2(8198,7286.47) ; U11.M21@8178.6,7272.32 ccw(c8178.6,7285) 8187.56,7276.04 ccw(c8196.53,7267.07) U11.M21@8183.85,7267.07 ; U11.E20@8217.97,6991.48 8237.49,7011 v2(8237.82,7011) U11.E19@8257.34,6991.48 ; U11.E20@8217.97,6996.73 ccw(c8217.97,7009.41) 8226.93,7000.45 ccw(c8235.9,6991.48) U11.E20@8223.22,6991.48 ; U11.AB20@8217.97,7660.77 v2(8235.2,7678) 8240.11,7678 U11.AB19@8257.34,7660.77 ; U11.E19@8252.09,6991.48 ccw(c8239.41,6991.48) 8248.37,7000.45 ccw(c8257.34,7009.41) U11.E19@8257.34,6996.73 ; U11.AB19@8252.09,7660.77 ccw(c8239.41,7660.77) 8248.37,7669.74 ccw(c8257.34,7678.7) U11.AB19@8257.34,7666.02 ; U11.F18@8296.71,7025.6 cw(c8296.71,7011.85) 8306.43,7021.57 ; U11.F18@8296.71,7030.85 8297.15,7030.85 v2(8317,7011) U11.E17@8336.08,6991.48 ; U11.AA18@8296.71,7621.4 U11.AB17@8336.08,7660.77 ; U11.AA18@8296.71,7626.65 ccw(c8296.71,7639.33) 8305.67,7630.37 ccw(c8314.64,7621.4) U11.AA18@8301.96,7621.4 ; U11.F18@8301.96,7030.85 ccw(c8313.57,7030.85) 8305.36,7022.64 ; U11.E17@8330.83,6991.54 ccw(c8318.15,6991.69) 8327.22,7000.55 ccw(c8336.28,7009.41) U11.E17@8336.14,6996.73 ; U11.AB17@8330.83,7660.77 cw(c8318.15,7660.77) 8327.11,7651.81 cw(c8336.08,7642.84) U11.AB17@8336.08,7655.52 ; v2(8395,7641.22) U11.AA15@8414.82,7621.4 ; U11.AA15@8409.57,7621.4 ccw(c8396.89,7621.4) 8405.85,7630.37 ccw(c8414.82,7639.33) U11.AA15@8414.82,7626.65 ; U11.F15@8414.82,7025.6 cw(c8414.82,7012.92) 8423.78,7021.88 cw(c8432.75,7030.85) U11.F15@8420.07,7030.85 ; U11.F15@8414.82,7030.85 v2(8434,7011.67) ; U11.B14@8454.19,6873.37 v2(8472,6855.56) ; U11.AE13@8493.47,7784.13 ccw(c8493.27,7796.81) 8502.38,7787.99 ccw(c8511.49,7779.17) U11.AE13@8498.81,7778.97 ; U11.AE13@8493.56,7778.88 v2(8514,7800) ; v2(8515,7012.92) U11.F12@8532.93,7030.85 ; U11.AA12@8532.93,7621.4 v2(8552,7640.47) ; U11.AA12@8532.93,7626.65 ccw(c8532.93,7639.33) 8541.89,7630.37 ccw(c8550.86,7621.4) U11.AA12@8538.18,7621.4 ; U11.E10@8611.67,6991.48 U11.F9@8651.04,7030.85 ; U11.E10@8611.67,6996.73 ccw(c8611.67,7009.41) 8620.63,7000.45 ccw(c8629.6,6991.48) U11.E10@8616.92,6991.48 ; U11.AB10@8611.67,7660.77 U11.AA9@8651.04,7621.4 ; U11.F9@8645.79,7030.85 cw(c8633.11,7030.85) 8642.07,7021.88 cw(c8651.04,7012.92) U11.F9@8651.04,7025.6 ; U11.AA9@8645.79,7621.4 ccw(c8633.11,7621.4) 8642.07,7630.37 ccw(c8651.04,7639.33) U11.AA9@8651.04,7626.65 ; U11.AB8@8690.41,7660.77 8710,7680.36 v2(8710,7680.55) U11.AB7@8729.78,7660.77 ; U11.AB8@8690.41,7666.02 ccw(c8690.41,7678.7) 8699.37,7669.74 ccw(c8708.34,7660.77) U11.AB8@8695.66,7660.77 ; U11.AB7@8724.53,7660.77 ccw(c8711.85,7660.77) 8720.81,7669.74 ccw(c8729.78,7678.7) U11.AB7@8729.78,7666.02 ; v2(8750,7286.22) U11.M6@8769.15,7267.07 ; U11.M6@8763.9,7267.07 ccw(c8751.22,7267.07) 8760.18,7276.04 ccw(c8769.15,7285) U11.M6@8769.15,7272.32 ; U11.R6@8769.15,7379.93 cw(c8769.15,7367.25) 8778.12,7376.22 cw(c8787.08,7385.18) U11.R6@8774.4,7385.18 ; U11.R6@8769.15,7385.18 v2(8788.33,7366) ; v2(8789,7483.44) U11.U5@8808.52,7463.92 ; v2(8789,7680.29) U11.AB5@8808.52,7660.77 ; 8800.73,7548.78 cw(c8794.62,7542.66) U11.W5@8803.27,7542.66 ; U11.U5@8803.27,7463.92 ccw(c8790.59,7463.92) 8799.55,7472.89 ccw(c8808.52,7481.85) U11.U5@8808.52,7469.17 ; U11.Y5@8803.27,7582.03 cw(c8790.59,7582.03) 8799.55,7573.07 cw(c8808.52,7564.1) U11.Y5@8808.52,7576.78 ; U11.AB5@8803.27,7660.77 ccw(c8790.59,7660.77) 8799.55,7669.74 ccw(c8808.52,7678.7) U11.AB5@8808.52,7666.02 ; U11.W5@8808.52,7542.66 8806.85,7542.66 v2(8788,7561.51) U11.Y5@8808.52,7582.03 ; v2(8828,6932.22) U11.D4@8847.89,6952.11 ; U11.D4@8842.64,6952.11 cw(c8829.96,6952.11) 8838.92,6943.14 cw(c8847.89,6934.18) U11.D4@8847.89,6946.86 ; U11.C3@8887.26,6907.49 cw(c8887.26,6894.81) 8896.23,6903.77 cw(c8905.19,6912.74) U11.C3@8892.51,6912.74 ; U11.C3@8887.26,6912.74 v2(8907,6893) ; U11.A2@8926.63,6834 U11.B1@8966,6873.37 U11.B2@8926.63,6873.37 ; U11.A2@8926.63,6839.25 ccw(c8926.63,6851.93) 8935.6,6842.97 ccw(c8944.56,6834) U11.A2@8931.88,6834 ; U11.N2@8926.63,7306.44 v2(8947,7326) ; U11.AE2@8926.63,7778.88 8946,7798.25 v2(8946,7800) ; U11.AE2@8926.63,7784.13 ccw(c8926.63,7796.81) 8935.6,7787.85 ccw(c8944.56,7778.88) U11.AE2@8931.88,7778.88 ; U11.AF2@8926.63,7818.25 U11.AE1@8966,7778.88 ; U11.N2@8926.74,7311.69 ccw(c8926.99,7324.37) 8935.78,7315.22 ccw(c8944.56,7306.08) U11.N2@8931.88,7306.33 ; U11.B2@8930.34,6869.66 cw(c8939.31,6860.69) 8939.31,6873.37 cw(c8939.31,6886.05) U11.B2@8930.34,6877.08 ; U11.B1@8960.75,6873.37 cw(c8948.07,6873.37) 8957.03,6864.4 cw(c8966,6855.44) U11.B1@8966,6868.12 ; U11.AE1@8960.75,7778.88 ccw(c8948.07,7778.88) 8957.03,7787.85 ccw(c8966,7796.81) U11.AE1@8966,7784.13 ; U11.B1@8962.29,6869.66 ccw(c8953.32,6860.69) 8953.32,6873.37 ccw(c8953.32,6886.05) U11.B1@8962.29,6877.08
  TopLayer w10: v2(8593.19,6973) U11.E10@8611.67,6991.48 ; U11.E10@8607.42,6991.48 cw(c8597.15,6991.48) 8604.41,6984.22 cw(c8611.67,6976.96) U11.E10@8611.67,6987.23 ; U11.E8@8690.41,6991.48 8692.82,6991.48 v2(8710,6972) U11.E7@8729.78,6991.48 ; U11.E7@8725.53,6991.51 cw(c8715.26,6991.59) 8722.47,6984.28 cw(c8729.67,6976.96) U11.E7@8729.75,6987.23 ; U11.J6@8769.15,7148.96 v2(8788.91,7168.72) U11.K5@8808.52,7188.33 ; U11.J6@8769.15,7153.21 ccw(c8769.15,7163.48) 8776.41,7156.22 ccw(c8783.67,7148.96) U11.J6@8773.4,7148.96 ; v2(8788,6972) U11.E5@8808.52,6991.48 ; U11.E5@8804.27,6991.59 cw(c8794.01,6991.86) 8801.08,6984.41 cw(c8808.14,6976.97) U11.E5@8808.41,6987.23 ; U11.K5@8804.27,7188.33 cw(c8794,7188.33) 8801.26,7181.07 cw(c8808.52,7173.81) U11.K5@8808.52,7184.08 ; U11.G5@8808.52,7070.22 8828,7089.7 v2(8828,7090.11) U11.H5@8808.52,7109.59 ; U11.G5@8808.52,7074.47 ccw(c8808.52,7084.74) 8815.78,7077.48 ccw(c8823.04,7070.22) U11.G5@8812.77,7070.22 ; U11.H5@8808.52,7105.34 cw(c8808.52,7095.07) 8815.78,7102.33 cw(c8823.04,7109.59) U11.H5@8812.77,7109.59
  TopLayer w12: C5.2@5070.32,6625.11 ccw(c5046.96,6648.47) 5080,6648.47 ccw(c5113.04,6648.47) C5.2@5089.68,6625.11 ; v3@5075.76,6653.76 cw(c5065.51,6643.51) 5080,6643.51 cw(c5094.49,6643.51) v3@5084.24,6653.76 ; v3(5080,6658) C5.2@5080,6613.46 5097.07,6630.53 U2.37@5170.72,6630.53 ; C5.2@5081.19,6614.24 cw(c5120.53,6574.91) 5120.53,6630.53 ; C5.2@5089.68,6605.76 cw(c5149.5,6545.94) U2.37@5149.5,6630.53 ; v3(5140,8854) 5151,8854 5182.77,8885.77 U1.112@5182.77,8922.31 ; v3@5140,8860 ccw(c5140,8901.04) 5169.02,8872.02 ; v3@5160,7652 cw(c5160,7637.51) 5170.24,7647.76 cw(c5180.49,7658) v3@5166,7658 ; v3(5160,7658) 5182.77,7635.23 U1.189@5182.77,7585.69 ; v3(5547,8858) 5576.47,8887.47 U1.92@5576.47,8922.31 ; v3@5547,8864 ccw(c5547,8878.49) 5557.24,8868.24 ccw(c5567.49,8858) v3@5553,8858 ; v3@5560,7636 cw(c5560,7621.51) 5570.24,7631.76 cw(c5580.49,7642) v3@5566,7642 ; v3(5560,7642) 5576.47,7625.53 U1.209@5576.47,7585.69 ; U2.12@5966,6630.53 6076,6630.53 C7.1@6086.54,6620 v3(6086.54,6674.54) ; U1.231@6009.54,7585.69 6009.54,7630.54 v3(6040,7661) ; U1.70@6009.54,8922.31 6009.54,8867.46 v3(6040,8837) ; 6026.09,6630.53 cw(c6026.09,6561.53) C7.1@6074.89,6610.32 ; v3@6034,7661 cw(c6019.51,7661) 6029.76,7650.76 cw(c6040,7640.51) v3@6040,7655 ; v3@6034,8837 ccw(c6019.51,8837) 6029.76,8847.24 ccw(c6040,8857.49) v3@6040,8843 ; 6055.07,6630.53 cw(c6055.07,6590.5) C7.1@6083.38,6618.81 ; C7.1@6076.86,6629.68 ccw(c6053.5,6653.04) 6086.54,6653.04 ccw(c6119.57,6653.04) C7.1@6096.21,6629.68 ; v3@6082.29,6670.29 cw(c6072.05,6660.05) 6086.54,6660.05 cw(c6101.02,6660.05) v3@6090.78,6670.29 ; v3(6100.33,7830.54) U1.9@6287.41,7830.54 ; v3@6104.57,7826.3 cw(c6114.82,7816.06) 6114.82,7830.54 cw(c6114.82,7845.03) v3@6104.57,7834.79 ; v3(6195.46,8657.54) U1.51@6274.31,8657.54 ; v3@6199.7,8653.3 cw(c6209.94,8643.06) 6209.94,8657.54 cw(c6209.94,8672.03) v3@6199.7,8661.79 ; C8.2@6200,6793.46 6200,6809 v3(6225,6834) ; C8.2@6201.66,6795.72 cw(c6226.28,6799.95) 6208.61,6817.61 ; C8.2@6213.49,6797.75 cw(c6254.24,6804.76) v3(6225,6834) ; v3@6219,6834 cw(c6204.51,6834) 6214.76,6823.76 cw(c6225,6813.51) v3@6225,6828 ; v3@6229.24,6829.76 cw(c6239.49,6819.51) 6239.49,6834 cw(c6239.49,6848.49) v3@6229.24,6838.24 ; U4.43@6279.23,6834 v3(6225,6834) ; U1.22@6287.1,8086.68 C10.1@6361,8088 6362,8089 v3(6362,8048) ; v1(6318.6,6777.6) U4.41@6318.6,6834 ; 6336.67,8087.56 ccw(c6336.28,8109.44) C10.1@6352.02,8094.25 ; 6336.88,8087.57 cw(c6337.27,8066) C10.1@6352.25,8081.52 ; C10.1@6354.64,8081.64 cw(c6336.86,8063.86) 6362,8063.86 ; v3@6357.76,8052.24 ccw(c6347.51,8062.49) 6362,8062.49 ccw(c6376.49,8062.49) v3@6366.24,8052.24 ; 6362,8068.69 cw(c6380.31,8068.69) C10.1@6367.36,8081.64 ; U4.49@6377.65,6364 v1(6377.65,6425.35) ; v1(6436.71,6763.29) U4.35@6436.71,6834 ; U4.55@6495.77,6364 v1(6495.77,6420.77) ; U4.29@6554.82,6834 6554.82,6779.18 6567,6767 v1(6717,6767) ; U4.15@6830.41,6834 6830.41,6886.41 6856,6912 6933,6912 v3(6948.52,6896.48) U4.9@6948.52,6834 ; U4.75@6889.47,6364 v1(6889.47,6409.47) ; v3@6942.52,6896.48 ccw(c6928.03,6896.48) 6938.28,6906.72 ccw(c6948.52,6916.97) v3@6948.52,6902.48 ; v3@6944.28,6892.24 cw(c6934.03,6881.99) 6948.52,6881.99 cw(c6963.01,6881.99) v3@6952.76,6892.24 ; U4.81@7007.57,6364 v1(7007.57,6415.57) ; U4.3@7066.56,6867.4 cw(c7072.28,6872.98) 7066.63,6878.63 ; U4.3@7066.54,6867.46 cw(c7093.26,6867.46) 7074.36,6886.36 ; U4.3@7066.63,6834 7066.63,6878.63 ; U4.1@7106,6834 7106,6884 v1(7089,6901) 7066.63,6878.63 ; U8.5@7299.6,7832.52 cw(c7300.09,7810.12) 7315.93,7825.96 ; U8.5@7299.86,7820.52 cw(c7300.94,7771.23) 7335.8,7806.09 ; U8.5@7300,7841.89 7341.89,7800 C19.2@7406.54,7800 7406.54,7900 R30.2@7400,7906.54 ; R30.2@7390.32,7894.89 cw(c7351.18,7855.75) v3@7406.54,7855.75 ; C19.2@7394.89,7790.32 ccw(c7371.53,7766.96) 7371.53,7800 ccw(c7371.53,7833.04) C19.2@7394.89,7809.68 ; C19.2@7396.86,7809.68 ccw(c7373.5,7833.04) 7406.54,7833.04 ccw(c7439.57,7833.04) C19.2@7416.21,7809.68 ; R30.2@7398.81,7903.38 cw(c7380.15,7884.72) 7406.54,7884.72 ; v3@7402.29,7850.76 cw(c7392.05,7840.51) 7406.54,7840.51 cw(c7421.02,7840.51) v3@7410.78,7850.76 ; v3@7402.29,7859.24 ccw(c7392.05,7869.49) 7406.54,7869.49 ccw(c7421.02,7869.49) v3@7410.78,7859.24 ; U14.1@8627.54,8552.46 ccw(c8597.46,8582.54) 8640,8582.54 ccw(c8682.54,8582.54) U14.1@8652.46,8552.46 ; v3@8635.76,8592.76 cw(c8625.51,8582.51) 8640,8582.51 cw(c8654.49,8582.51) v3@8644.24,8592.76 ; U14.1@8640,8540 v3(8640,8597) ; FB4.1@8916.74,8885.44 cw(c8893.11,8862.36) 8926.14,8861.96 cw(c8959.18,8861.57) FB4.1@8936.1,8885.21 ; v3@8921.81,8854.29 ccw(c8911.69,8864.66) 8926.17,8864.48 ccw(c8940.66,8864.31) v3@8930.29,8854.19 ; v3(8926,8850) FB4.1@8926.54,8895 ; R56.2@9163.79,6630.32 cw(c9140.43,6606.96) 9173.46,6606.96 cw(c9206.5,6606.96) R56.2@9183.14,6630.32 ; v3@9169.22,6594.24 ccw(c9158.98,6604.49) 9173.46,6604.49 ccw(c9187.95,6604.49) v3@9177.71,6594.24 ; v3(9173.47,6590) R56.2@9173.46,6640 ; U17.8@9442.36,7875 9558.46,7875 C37.2@9560,7873.46 v2(9560,7928) ; U17.8@9477.97,7870.89 cw(c9487.89,7860.97) 9487.89,7875 cw(c9487.89,7889.03) U17.8@9477.97,7879.11 ; 9525.92,7875 ccw(c9525.92,7909.52) 9550.32,7885.11 ccw(c9526.96,7908.47) 9560,7908.47 ccw(c9593.04,7908.47) C37.2@9569.68,7885.11 ; 9528.01,7875 cw(c9528.01,7843.44) C37.2@9550.32,7865.76
  TopLayer w16: C2.1@4640,8393.46 4640,8388.2 v3(4682.13,8346.07) ; DL2.13@4792.1,7890.1 DL2.13@4759.3,7890.1 v3@4818.1,7890.1 ; C20.1@7827.36,6774.92 ccw(c7812.62,6798) 7840,6798 ; C20.1@7840,6755.12 7840,6798 ; C20.1@7852.64,6774.92 cw(c7867.38,6798) 7840,6798 ; C21.1@7918.88,7960 7918.88,7841.75 U11.AE26@7981.75,7778.88 ; U11.B26@7981.75,6873.37 7915.37,6873.37 7840,6798 ; U11.B1@8966,6873.37 8979.37,6860 9026.26,6860 v3(9039.63,6873.37) ; 8997.69,6860 ccw(c8997.69,6915.31) v3@9036.8,6876.2
  TopLayer w20: U6.4@6964,8220 6977.46,8206.54 v3(7189.54,8206.54) ; U6.4@6990.31,8226.63 ccw(c7038.81,8275.13) 7038.81,8206.54 ; U6.4@7004.45,8199.23 cw(c7022.08,8181.6) U6.4@7022.08,8206.54 ; U6.4@7004.45,8240.77 ccw(c7087.1,8323.41) 7087.1,8206.54 ; C16.2@7113.15,8199.69 ccw(c7096.62,8183.15) 7096.62,8206.54 ccw(c7096.62,8229.92) C16.2@7113.15,8213.38 ; C16.2@7126.85,8199.69 cw(c7143.38,8183.15) 7143.38,8206.54 cw(c7143.38,8229.92) C16.2@7126.85,8213.38
  TopLayer w40: C12.1@6880,9417 C12.1@6880.05,9417
  BottomLayer w6: v3(8586,6660) R81.2@8646.54,6660 ; v3@8592.36,6653.64 cw(c8607.73,6638.27) 8607.73,6660 cw(c8607.73,6681.73) v3@8592.36,6666.36 ; R81.2@8632.77,6648.2 ccw(c8604.29,6619.72) 8604.29,6660 ccw(c8604.29,6700.28) R81.2@8632.77,6671.8 ; R81.2@8637.01,6652.44 ccw(c8618.77,6634.2) 8618.77,6660 ccw(c8618.77,6685.8) R81.2@8637.01,6667.56 ; R80.2@8834.74,8188.2 cw(c8806.25,8159.72) 8846.54,8159.72 cw(c8886.82,8159.72) R80.2@8858.33,8188.2 ; R80.2@8838.98,8192.44 cw(c8820.74,8174.2) 8846.54,8174.2 cw(c8872.33,8174.2) R80.2@8854.09,8192.44 ; v1@8843,8163.07 ccw(c8834.46,8171.61) 8846.54,8171.61 ccw(c8858.61,8171.61) v1@8850.07,8163.07 ; v1(8846.54,8159.54) R80.2@8846.54,8200 ; R82.2@8901.67,8111.8 ccw(c8873.18,8140.28) 8913.46,8140.28 ccw(c8953.75,8140.28) R82.2@8925.26,8111.8 ; R82.2@8905.91,8107.56 ccw(c8887.67,8125.8) 8913.46,8125.8 ccw(c8939.26,8125.8) R82.2@8921.02,8107.56 ; v1@8909.93,8137.93 cw(c8901.39,8129.39) 8913.46,8129.39 cw(c8925.54,8129.39) v1@8917,8137.93 ; R82.2@8913.46,8100 v1(8913.46,8141.46)
  BottomLayer w8: R63.1@5286.37,6168.09 ccw(c5259.6,6194.87) 5297.46,6194.87 ccw(c5335.33,6194.87) R63.1@5308.56,6168.09 ; R64.1@5286.37,6265.91 cw(c5259.6,6239.13) 5297.46,6239.13 cw(c5335.33,6239.13) R64.1@5308.56,6265.91 ; v2@5293.22,6215.76 cw(c5282.98,6205.51) 5297.46,6205.51 cw(c5311.95,6205.51) v2@5301.71,6215.76 ; v2@5293.22,6224.24 ccw(c5282.98,6234.49) 5297.46,6234.49 ccw(c5311.95,6234.49) v2@5301.71,6224.24 ; R63.1@5297.46,6157 R64.1@5297.46,6283.54 ; C91.1@8000,7780 8020,7780 ; C91.1@8009.29,7774.11 cw(c8020,7767.32) 8020,7780 ; C91.1@8009.29,7785.89 ccw(c8020,7792.68) 8020,7780 ; C93.1@8040,6860 8040.55,6860.55 v2(8040.55,6892.81) ; v2(8040,7760) 8020,7780 ; C96.1@8099.86,7660.77 8118.71,7679.63 v2(8120.37,7679.63) 8120.37,7719.63 C97.1@8120,7720 ; C94.1@8100,6962 8110,6972 v2(8120,6972) ; C95.1@8100,7600 8120,7580 v2(8120,7561.89) ; C95.1@8102.5,7589 cw(c8102.5,7568.48) 8117.01,7582.99 ; C95.1@8113.35,7598.17 ccw(c8132.44,7594.95) 8118.75,7581.25 ; v2(8119.64,7090) 8150,7090 C99.1@8160,7100 ; v2(8120,7207.56) 8132.44,7220 C100.1@8160,7220 ; 8137.09,7090 ccw(c8137.09,7117.24) C99.1@8157.73,7099.46 ; C101.1@8140,7380 8156,7364 v2(8157.42,7364) ; C100.1@8152.22,7212.22 ccw(c8133.44,7193.44) 8133.44,7220 ccw(c8133.44,7246.56) C100.1@8152.22,7227.78 ; v2(8158.69,7483.39) 8158.69,7518.69 C102.1@8160,7520 ; C103.1@8180,7706.5 cw(c8180,7673.91) 8203.05,7696.95 ; C103.1@8180,7720 8222,7678 8238,7678 C109.1@8240,7720 ; C103.1@8191,7717.5 ccw(c8211.52,7717.5) 8197.01,7702.99 ; v2(8237.82,7011) 8240,7008.82 C98.1@8240,6980 ; v2(8317,7011) 8317,7003 C110.1@8340,6980 ; 8322.99,6997.01 cw(c8308.48,6982.5) C110.1@8329,6982.5 ; v2(8395,7641.22) 8401.22,7641.22 C116.1@8420,7660 ; v2(8434,7011.67) 8434,6988 C119.1@8440,6982 ; C127.1@8480,7740 8473,7747 8493,7773 v2(8514,7800) ; C127.1@8482.65,7743.91 cw(c8496.94,7751.55) 8484.1,7761.43 ; C127.1@8489.7,7747.68 cw(c8508.95,7757.95) 8491.66,7771.25 ; C120.1@8515,6998.71 ccw(c8528.62,6998.71) C120.1@8521.56,6987.06 ; v2(8515,7012.92) 8515,6987 C120.1@8520,6982 ; C132.1@8540,7680 8552,7668 v2(8552,7640.47) ; C132.1@8542.41,7681.88 cw(c8533.48,7665.65) C132.1@8552,7665.65 ; C133.1@8617.88,7693.38 cw(c8588.62,7664.12) 8630,7664.12 ; C133.1@8620,7698 8630,7688 v2(8630,7643) ; C133.1@8623.54,7699.04 cw(c8607.93,7683.43) C133.1@8630,7683.43 ; C139.1@8679.21,7700.44 cw(c8682.15,7682.01) 8695.35,7695.2 ; C134.1@8679.95,6953.5 ccw(c8679.8,6981.98) 8700.04,6961.94 ; C134.1@8680,6940 8680,6941.7 v2(8710,6972) ; C139.1@8680,7698 8692.55,7698 v2(8710,7680.55) ; C134.1@8691,6942.55 cw(c8715.64,6942.68) 8698.13,6960.01 ; v2(8789,7680.29) 8806.71,7698 C144.1@8820,7698 ; 8803.48,7694.77 cw(c8817.72,7680.53) C144.1@8820.75,7700.44 ; C145.1@8900,7820 8920,7800 v2(8946,7800) ; C145.1@8900.69,7806.52 cw(c8902.36,7779.86) 8921.25,7798.75 ; C145.1@8911,7817.5 ccw(c8931.52,7817.5) 8917.01,7802.99
  BottomLayer w10: C140.1@8760,6980 8770,6970 v2(8788,6972) ; C141.1@8780,7140 8780,7159.81 v2(8788.91,7168.72)
  BottomLayer w12: R65.2@5133.46,8340 5178,8340 v3(5193,8325) ; C48.1@5133.64,8828.86 ccw(c5118.27,8844.23) 5140,8844.23 ccw(c5161.73,8844.23) C48.1@5146.36,8828.86 ; v3@5135.76,8849.76 cw(c5125.51,8839.51) 5140,8839.51 cw(c5154.49,8839.51) v3@5144.24,8849.76 ; C48.1@5140,8820 v3(5140,8854) ; R65.2@5145.11,8330.32 cw(c5168.47,8306.96) 5168.47,8340 cw(c5168.47,8373.04) R65.2@5145.11,8349.68 ; C44.1@5153.64,7691.14 cw(c5138.27,7675.77) 5160,7675.77 cw(c5181.73,7675.77) C44.1@5166.36,7691.14 ; v3@5155.76,7662.24 ccw(c5145.51,7672.49) 5160,7672.49 ccw(c5174.49,7672.49) v3@5164.24,7662.24 ; v3(5160,7658) C44.1@5160,7700 ; v3@5187,8325 ccw(c5172.51,8325) 5182.76,8335.24 ccw(c5193,8345.49) v3@5193,8331 ; v3@5542.76,8853.76 cw(c5532.51,8843.51) 5547,8843.51 cw(c5561.49,8843.51) v3@5551.24,8853.76 ; 5547,8838.64 ccw(c5568.02,8838.64) C57.1@5558.66,8819.81 ; C56.1@5553.64,7691.14 cw(c5538.27,7675.77) 5560,7675.77 cw(c5581.73,7675.77) C56.1@5566.36,7691.14 ; v3@5555.76,7646.24 ccw(c5545.51,7656.49) 5560,7656.49 ccw(c5574.49,7656.49) v3@5564.24,7646.24 ; v3(5560,7642) C56.1@5560,7700 ; C57.1@5560,8820 5547,8833 v3(5547,8858) ccw(c5577.64,8858) C57.1@5564.01,8830.56 ; C75.1@6033.64,7691.14 cw(c6018.27,7675.77) 6040,7675.77 cw(c6061.73,7675.77) C75.1@6046.36,7691.14 ; v3@6035.76,7665.24 ccw(c6025.51,7675.49) 6040,7675.49 ccw(c6054.49,7675.49) v3@6044.24,7665.24 ; C77.1@6035.76,8832.76 cw(c6025.51,8822.51) 6040,8822.51 cw(c6054.49,8822.51) C77.1@6044.24,8832.76 ; v3(6040,7661) C75.1@6040,7700 ; C77.1@6040,8820 v3(6040,8837) ; C71.1@6058,7838 6080,7838 ; C71.1@6066.28,7831.83 cw(c6081.37,7799.27) v3@6093.73,7832.96 ; C71.1@6068.86,7833.64 cw(c6079.4,7823.1) 6079.4,7838 ; C71.1@6069.42,7834.25 cw(c6077.71,7827.35) 6081.43,7837.48 ; C71.1@6070.61,7843.9 ccw(c6080,7848.42) 6080,7838 ; v3@6094.89,7828.02 ccw(c6081.74,7821.93) 6086.73,7835.53 ccw(c6091.72,7849.13) v3@6097.81,7835.99 ; v3(6100.33,7830.54) 6080,7838 ; C73.1@6140,8660 6193,8660 v3(6195.46,8657.54) ; C73.1@6148.86,8653.64 cw(c6164.23,8638.27) 6164.23,8660 cw(c6164.23,8681.73) C73.1@6148.86,8666.36 ; 6175.04,8660 cw(c6175.04,8637.13) v3@6191.21,8653.3 ; C79.2@6353.46,6460 6377.65,6435.81 v1(6377.65,6425.35) ; C79.2@6355.2,6458.33 cw(c6351.67,6432.59) v1@6377.65,6432.59 ; C79.2@6355.43,6446.32 cw(c6355.43,6418.03) 6375.43,6438.03 ; C79.2@6366.84,6446.62 cw(c6345.56,6425.35) v1@6375.65,6425.35 ; C79.2@6369.04,6458.51 ccw(c6395.48,6455.61) 6376.67,6436.79 ; C80.2@6425.76,6689.68 ccw(c6399.31,6716.12) 6436.71,6716.12 ; 6436.71,6709.96 ccw(c6465.39,6709.96) C80.2@6445.11,6689.68 ; v1(6436.71,6763.29) 6436.71,6696.75 C80.2@6440,6693.46 ; v1@6495.76,6417.73 cw(c6527.16,6417.73) C81.2@6516.25,6447.17 ; v1(6495.77,6420.77) 6495.77,6442.3 C81.2@6513.46,6460 ; 6495.77,6434.97 cw(c6520.77,6434.97) C81.2@6512.08,6458.42 ; v3@6741,8090 cw(c6741,8075.51) 6751.24,8085.76 cw(c6761.49,8096) v3@6747,8096 ; v3(6741,8096) 6755,8082 U19.3@6755,8017.64 ; U19.3@6750.89,8053.24 ccw(c6740.97,8063.16) 6755,8063.16 ccw(c6769.03,8063.16) U19.3@6759.11,8053.24 ; U19.7@6800.89,8257.97 ccw(c6790.97,8267.89) 6805,8267.89 ccw(c6819.03,8267.89) U19.7@6809.11,8257.97 ; U19.7@6805,8222.36 6805,8273 6817,8285 v3(6833,8285) 6855,8263 U19.8@6855,8222.36 ; 6809,8277 cw(c6821.33,8264.67) v3@6830.01,8279.8 ; 6816.41,8284.41 cw(c6832.35,8268.46) v3@6833.23,8291 ; 6820.09,8288.09 cw(c6829.42,8278.76) v3@6835.99,8290.2 ; v3@6828.76,8280.76 ccw(c6818.51,8270.51) 6818.51,8285 ccw(c6818.51,8299.49) v3@6828.76,8289.24 ; v3@6833,8279 cw(c6833,8264.51) 6843.24,8274.76 cw(c6853.49,8285) v3@6839,8285 ; v3@6838.62,8279.38 cw(c6813.09,8253.86) U19.8@6849.19,8253.86 ; v1(6889.47,6409.47) C82.2@6943,6458 ; 6919.61,6436.8 ccw(c6896.44,6462.36) C82.2@6930.9,6460.67 ; 6921.15,6438.19 cw(c6942.35,6414.8) C82.2@6943.9,6446.33 ; v1(7089,6901) 7108,6920 C84.2@7126.54,6920 ; 7097.52,6909.52 cw(c7119.64,6887.4) C84.2@7124.32,6918.33
  BottomLayer w16: v3(4682.13,8346.07) 4698.1,8330.1 DL1.4@4760.7,8330.1 ; v3(4819,7890) 4822.46,7893.46 C1.1@4860,7893.46 ; 7706.54,8060 R76.1@7706.54,8160 ; v2(8946,7800) 8990.88,7844.88 C146.1@9020,7844.88 ; 8960.55,7814.55 cw(c9015.68,7759.43) C146.1@9016.03,7837.39 ; v3(9039.63,6873.37) 9064.06,6873.37 C147.1@9100,6837.43 ; 9062.1,6875.34 cw(c9034.67,6847.91) C147.1@9072.9,6841.39 ; 9062.67,6874.76 ccw(c9096.06,6908.15) C147.1@9096.06,6860.93
  other v2: 5297.46,6220 7900,6858 8631,7012 8316.21,7640.91 7918.88,7879
  other v3: 7406.54,7855 6888,8073.46 7706.54,8101 6864,9322 6899,9323 6881,9357 6796,9420 6827,9421 4951,9500
V5: C14.1 C18.2 C30.1 C31.1 C43.1 C148.1 D1.1 J3.1 J4.A1 J4.A25 J4.B2 J4.B24 J4.D3 J4.D23 J4.E1 J4.E25 JP13.12 R44.2 R45.1 R46.2 R57.2 U7.2 U9.3 U13.14 U13.15 U13.16 U18.3 | length 2975.8
  TopLayer w12: R45.1@8153.46,9600 v3(8215,9600) ; R46.2@8153.46,9700 v3(8214,9700) ; R45.1@8165.11,9590.32 cw(c8188.47,9566.96) 8188.47,9600 cw(c8188.47,9633.04) R45.1@8165.11,9609.68 ; R46.2@8165.11,9690.32 cw(c8188.47,9666.96) 8188.47,9700 cw(c8188.47,9733.04) R46.2@8165.11,9709.68 ; v3@8209.76,9695.76 ccw(c8199.51,9685.51) 8199.51,9700 ccw(c8199.51,9714.49) v3@8209.76,9704.24 ; v3@8210.76,9595.76 ccw(c8200.51,9585.51) 8200.51,9600 ccw(c8200.51,9614.49) v3@8210.76,9604.24 ; v3(8214.46,9386.54) R44.2@8260,9386.54 ; v3@8218.71,9382.29 cw(c8228.95,9372.05) 8228.95,9386.54 cw(c8228.95,9401.02) v3@8218.71,9390.78 ; R44.2@8250.32,9376.86 ccw(c8226.96,9353.5) 8226.96,9386.54 ccw(c8226.96,9419.57) R44.2@8250.32,9396.21 ; C31.1@8586,9751 v3(8649,9751) ; C31.1@8587,9675 8645,9675 cw(c8645,9709.3) C31.1@8612.05,9699.76 ; C31.1@8588,9719 v3(8648,9719) ; C31.1@8596.28,9763.37 ccw(c8623.04,9786.13) 8623.04,9751 ; C31.1@8596.59,9706.53 cw(c8622.79,9685.24) 8622.79,9719 ; C31.1@8597.21,9732.67 ccw(c8624.26,9752.59) 8624.26,9719 ; C31.1@8597.2,9736.84 cw(c8625.23,9716.16) 8625.23,9751 ; C31.1@8600.53,9696.42 ccw(c8629.03,9704.67) 8629.03,9675 ; C31.1@8603.6,9666.88 cw(c8623.21,9647.26) 8623.21,9675 ; C31.1@8605.42,9771.15 ccw(c8649,9808.2) v3(8649,9751) ; C31.1@8605.9,9698.96 cw(c8648,9664.77) v3(8648,9719) ; C31.1@8606.85,9729.72 cw(c8649,9698.63) v3(8649,9751) ; C31.1@8606.87,9739.79 ccw(c8648,9770.08) v3(8648,9719) ; C31.1@8610.37,9675 ccw(c8610.37,9723.63) v3@8644.76,9689.24 ; 8639.34,9675 ccw(c8639.34,9694.66) v3@8653.24,9680.76 ; v3@8643.76,9714.76 ccw(c8633.51,9704.51) 8633.51,9719 ccw(c8633.51,9733.49) v3@8643.76,9723.24 ; v3@8644.76,9746.76 ccw(c8634.51,9736.51) 8634.51,9751 ccw(c8634.51,9765.49) v3@8644.76,9755.24 ; R57.2@8790.32,9025.11 ccw(c8766.96,9048.47) 8800,9048.47 ccw(c8833.04,9048.47) R57.2@8809.68,9025.11 ; v3@8795.76,9066.76 cw(c8785.51,9056.51) 8800,9056.51 cw(c8814.49,9056.51) v3@8804.24,9066.76 ; R57.2@8800,9013 v3(8800,9071)
  TopLayer w40: v4(6920,9634) 6990.88,9634 7071.88,9553 v3@7320,9553 ; 6946.3,9634 cw(c6946.3,9575.12) C148.1@6987.93,9616.75 ; C148.1@7015.43,9624.88 ccw(c7052.69,9624.88) C148.1@7026.35,9598.54 ; 7039.93,9584.95 ccw(c7105,9650.03) U7.2@7105,9558 ; U9.3@7330,9039 C18.2@7452.46,9039 ; C18.2@7460,9046.54 7561.65,9046.54 7576.12,9061 v4(7728,9061) ; 7504.02,9046.54 ccw(c7504.02,9136.93) C14.1@7567.93,9073.01 ; C14.1@7592.07,9073.01 ccw(c7621.06,9102.01) 7621.06,9061
  BottomLayer w12: D1.1@9526.15,6168.75 cw(c9492.7,6135.3) 9540,6135.3 cw(c9587.3,6135.3) D1.1@9553.85,6168.75 ; v3@9535.76,6125.24 ccw(c9525.51,6135.49) 9540,6135.49 ccw(c9554.49,6135.49) v3@9544.24,6125.24 ; v3(9540,6121) D1.1@9540,6182.6 v3(9592.6,6130) ; D1.1@9543.94,6163.01 cw(c9543.94,6125.22) 9570.66,6151.94 ; D1.1@9563.53,6182.6 ccw(c9620.33,6182.6) 9580.16,6142.43 ; v3@9586.6,6130 ccw(c9572.11,6130) 9582.36,6140.24 ccw(c9592.6,6150.49) v3@9592.6,6136
  BottomLayer w40: U18.3@4930,9021 4973,9021 4996.88,9044.88 C43.1@5120,9044.88 ; U18.3@4954,9022 ccw(c4954,9070.28) 4988.14,9036.14 ; 4977,9025 cw(c5025,8977) v4(5025,9044.88) ccw(c5017.97,8995.68) 4982.82,9030.82
  other v3: 7309,9553 8649,9685
  other v4: 7664,9061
